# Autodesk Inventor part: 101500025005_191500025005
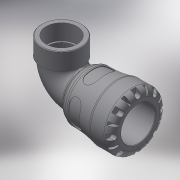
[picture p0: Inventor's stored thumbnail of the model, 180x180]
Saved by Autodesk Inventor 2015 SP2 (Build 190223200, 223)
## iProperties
Created: 2016-12
Part Number: 101500025005_191500025005
Material: Generic
Description: PLASSON 90° ELBOW WITH THREADED FEMALE OFFTAKE 25X1/2" SERIES 1
Document SubType Name: Modeling
Designer: KIM
Mass: 557.611 g
Surface Area: 990.043 cm^2
Volume: 557.611 cm^3
Density: 1 g/cm^3
Appearance: Default
Author: KIM
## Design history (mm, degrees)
derived "1015.ipt"
feature "Solid1::1015.ipt"
tag "TaggingFeature1"
body "Solid1"
other parameters: "d1" = 20.16, "d2" = 25, "d3" = 31.25, "d4" = 47, "d8" = 41.36, "d13" = 6.3, "d14" = 6.3, "d15" = 0, "d17" = 360 deg, "d19" = 8 deg, "d20" = 0.5, "d21" = 0.5, "d22" = 8 deg, "d24" = 0, "d26" = 360 deg, "d33" = 4.7, "d43" = 38.54, "d51" = 0.47, "d54" = 8.75, "d55" = 5.5, "d57" = 12.348, "d58" = 0, "d74" = 0, "d78" = 48, "d82" = 0.5, "d115" = 360 deg, "d207" = 90 deg, "d228" = 7.4375, "d247" = 0.94, "d248" = 2.88, "d268" = 22.748, "d269" = 2.88, "d270" = 74, "d281" = 2.79465, "d294" = 18.631, "d295" = 17, "d296" = 18.7, "d297" = 16.7679, "d299" = 21.79827, "d300" = 16.7679, "d301" = 0, "d302" = 0, "d303" = 8.37086, "d306" = 0, "d307" = 9, "d308" = 8, "d310" = 3, "d_" = 25, "E_" = 47, "l_" = 48, "A_" = 74, "l_2" = 17, "Rp_" = 18.631, "d9" = 7.875, "d11" = 47, "d12" = 31.25, "d298" = 24.2203
